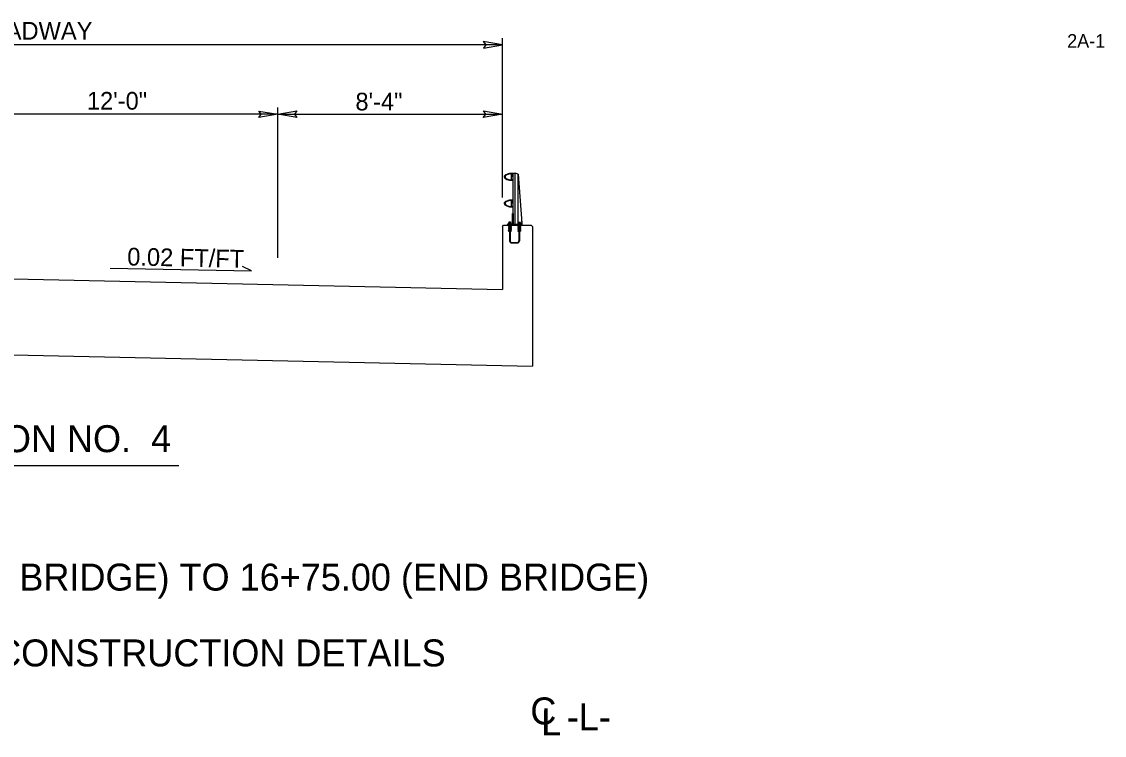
# Model space of a CAD drawing. Extents: x 1901984 to 1902132, y 194049 to 194156.
# Drawn here: x 1902088.64 to 1902128.82, y 194129.22 to 194155.68 of the extents above; entities that cross this region are included whole.
import ezdxf

# ---------------------------------------------------------------- set-up
doc = ezdxf.new("R2010")
doc.units = 0
for name, color, linetype in [('Old_Level_1', 7, 'Continuous'), ('Old_Level_11', 7, 'Continuous'), ('Old_Level_2', 7, 'Continuous'), ('Old_Level_44', 7, 'Continuous'), ('Scratch_Level_3', 7, 'Continuous'), ('Sheet PE Seal Cell', 7, 'Continuous')]:
    doc.layers.add(name, color=color, linetype=linetype)

# ---------------------------------------------------------------- blocks, each defined once
blk = doc.blocks.new('TERMINATOR')
at = {"layer": 'Scratch_Level_3'}
blk.add_lwpolyline([(-0.469, 0.081), (0, 0), (-0.471, -0.083), (-0.411, 0)], close=True, dxfattribs=at)

msp = doc.modelspace()

# ---------------------------------------------------------------- linework, layer by layer
at = {"layer": 'Old_Level_1'}
for p, q in [((1902106.478, 194154.823), (1902065.811, 194154.823)), ((1902106.478, 194149.16), (1902106.478, 194155.073)), ((1902098.144, 194146.923), (1902098.144, 194152.498)), ((1902098.144, 194152.248), (1902086.144, 194152.248)), ((1902098.144, 194152.249), (1902106.478, 194152.249)), ((1902091.931, 194146.546), (1902097.164, 194146.441)), ((1902097.164, 194146.441), (1902096.83, 194146.608)), ((1902086.144, 194146.196), (1902106.478, 194145.745)), ((1902086.563, 194143.369), (1902107.596, 194142.901))]:
    msp.add_line(p, q, dxfattribs=at)
at = {"layer": 'Old_Level_11'}
msp.add_line((1902077.852, 194139.224), (1902094.478, 194139.224), dxfattribs=at)
at = {"layer": 'Sheet PE Seal Cell'}
for p, q in [((1902106.813, 194150.028), (1902106.813, 194149.926)), ((1902106.876, 194150.059), (1902106.952, 194150.059)), ((1902106.876, 194148.176), (1902106.876, 194150.059)), ((1902107.066, 194150.022), (1902106.952, 194150.059)), ((1902106.952, 194148.176), (1902106.952, 194150.059)), ((1902107.066, 194148.176), (1902107.066, 194150.022)), ((1902107.066, 194150.022), (1902107.197, 194148.214)), ((1902106.813, 194149.824), (1902106.813, 194149.926)), ((1902106.813, 194149.041), (1902106.813, 194148.939)), ((1902106.813, 194148.837), (1902106.813, 194148.939)), ((1902107.066, 194149.158), (1902107.07, 194149.158)), ((1902106.478, 194148.089), (1902106.526, 194148.138)), ((1902106.478, 194148.089), (1902106.478, 194145.745)), ((1902106.526, 194148.138), (1902107.547, 194148.138)), ((1902106.705, 194148.102), (1902106.805, 194148.102)), ((1902106.705, 194148.091), (1902106.805, 194148.091)), ((1902106.705, 194148.058), (1902106.747, 194148.058)), ((1902106.705, 194148.047), (1902106.747, 194148.047)), ((1902106.705, 194148.013), (1902106.747, 194148.013)), ((1902106.705, 194148.002), (1902106.747, 194148.002)), ((1902106.727, 194148.08), (1902106.747, 194148.08)), ((1902106.727, 194148.069), (1902106.747, 194148.069)), ((1902106.727, 194148.035), (1902106.747, 194148.035)), ((1902106.727, 194148.024), (1902106.747, 194148.024)), ((1902106.727, 194147.991), (1902106.747, 194147.991)), ((1902106.727, 194147.98), (1902106.747, 194147.98)), ((1902106.73, 194148.102), (1902106.73, 194148.186)), ((1902106.732, 194148.226), (1902106.732, 194148.262)), ((1902106.732, 194148.262), (1902106.775, 194148.262)), ((1902106.747, 194148.08), (1902106.763, 194148.08)), ((1902106.747, 194148.08), (1902106.747, 194147.549)), ((1902106.763, 194148.08), (1902106.783, 194148.08)), ((1902106.763, 194148.08), (1902106.763, 194147.549)), ((1902106.763, 194148.069), (1902106.783, 194148.069)), ((1902106.763, 194148.058), (1902106.805, 194148.058)), ((1902106.763, 194148.047), (1902106.805, 194148.047)), ((1902106.763, 194148.035), (1902106.783, 194148.035)), ((1902106.763, 194148.024), (1902106.783, 194148.024)), ((1902106.763, 194148.013), (1902106.805, 194148.013)), ((1902106.763, 194148.002), (1902106.805, 194148.002)), ((1902106.763, 194147.991), (1902106.783, 194147.991)), ((1902106.763, 194147.98), (1902106.783, 194147.98)), ((1902106.775, 194148.262), (1902106.775, 194148.226)), ((1902106.777, 194148.102), (1902106.777, 194148.186)), ((1902107.053, 194148.102), (1902107.154, 194148.102)), ((1902107.053, 194148.091), (1902107.154, 194148.091)), ((1902107.053, 194148.058), (1902107.095, 194148.058)), ((1902107.053, 194148.047), (1902107.095, 194148.047)), ((1902107.053, 194148.013), (1902107.095, 194148.013)), ((1902107.053, 194148.002), (1902107.095, 194148.002)), ((1902107.076, 194148.08), (1902107.095, 194148.08)), ((1902107.076, 194148.069), (1902107.095, 194148.069)), ((1902107.076, 194148.035), (1902107.095, 194148.035)), ((1902107.076, 194148.024), (1902107.095, 194148.024)), ((1902107.076, 194147.991), (1902107.095, 194147.991)), ((1902107.076, 194147.98), (1902107.095, 194147.98)), ((1902107.081, 194148.217), (1902107.081, 194148.252)), ((1902107.081, 194148.252), (1902107.124, 194148.252)), ((1902107.081, 194148.093), (1902107.081, 194148.176)), ((1902107.095, 194148.08), (1902107.112, 194148.08)), ((1902107.095, 194148.08), (1902107.095, 194147.549)), ((1902107.112, 194148.08), (1902107.131, 194148.08)), ((1902107.112, 194148.08), (1902107.112, 194147.549)), ((1902107.112, 194148.069), (1902107.131, 194148.069)), ((1902107.112, 194148.058), (1902107.154, 194148.058)), ((1902107.112, 194148.047), (1902107.154, 194148.047)), ((1902107.112, 194148.035), (1902107.131, 194148.035)), ((1902107.112, 194148.024), (1902107.131, 194148.024)), ((1902107.112, 194148.013), (1902107.154, 194148.013)), ((1902107.112, 194148.002), (1902107.154, 194148.002)), ((1902107.112, 194147.991), (1902107.131, 194147.991)), ((1902107.112, 194147.98), (1902107.131, 194147.98)), ((1902107.124, 194148.252), (1902107.124, 194148.217)), ((1902107.125, 194148.093), (1902107.125, 194148.176)), ((1902107.194, 194148.235), (1902107.194, 194148.268)), ((1902107.197, 194148.176), (1902107.197, 194148.214)), ((1902107.547, 194148.138), (1902107.596, 194148.089)), ((1902107.596, 194148.089), (1902107.596, 194142.901)), ((1902106.705, 194147.969), (1902106.747, 194147.969)), ((1902106.705, 194147.958), (1902106.747, 194147.958)), ((1902106.705, 194147.924), (1902106.747, 194147.924)), ((1902106.705, 194147.913), (1902106.747, 194147.913)), ((1902106.727, 194147.946), (1902106.747, 194147.946)), ((1902106.727, 194147.935), (1902106.747, 194147.935)), ((1902106.763, 194147.969), (1902106.805, 194147.969)), ((1902106.763, 194147.958), (1902106.805, 194147.958)), ((1902106.763, 194147.946), (1902106.783, 194147.946)), ((1902106.763, 194147.935), (1902106.783, 194147.935)), ((1902106.763, 194147.924), (1902106.805, 194147.924)), ((1902106.763, 194147.913), (1902106.805, 194147.913)), ((1902107.053, 194147.969), (1902107.095, 194147.969)), ((1902107.053, 194147.958), (1902107.095, 194147.958)), ((1902107.053, 194147.924), (1902107.095, 194147.924)), ((1902107.053, 194147.913), (1902107.095, 194147.913)), ((1902107.076, 194147.946), (1902107.095, 194147.946)), ((1902107.076, 194147.935), (1902107.095, 194147.935)), ((1902107.112, 194147.969), (1902107.154, 194147.969)), ((1902107.112, 194147.958), (1902107.154, 194147.958)), ((1902107.112, 194147.946), (1902107.131, 194147.946)), ((1902107.112, 194147.935), (1902107.131, 194147.935)), ((1902107.112, 194147.924), (1902107.154, 194147.924)), ((1902107.112, 194147.913), (1902107.154, 194147.913)), ((1902106.817, 194147.496), (1902107.042, 194147.496)), ((1902106.817, 194147.479), (1902107.042, 194147.479))]:
    msp.add_line(p, q, dxfattribs=at)
for points in [[(1902106.876, 194149.796), (1902106.876, 194149.844), (1902106.856, 194149.844), (1902106.856, 194149.836), (1902106.858, 194149.836), (1902106.858, 194149.816), (1902106.826, 194149.816), (1902106.822, 194149.847), (1902106.822, 194149.926), (1902106.822, 194150.005), (1902106.826, 194150.036), (1902106.858, 194150.036), (1902106.858, 194150.016), (1902106.856, 194150.016), (1902106.856, 194150.008), (1902106.876, 194150.008), (1902106.876, 194150.057)], [(1902106.876, 194148.808), (1902106.876, 194148.857), (1902106.856, 194148.857), (1902106.856, 194148.849), (1902106.858, 194148.849), (1902106.858, 194148.829), (1902106.826, 194148.829), (1902106.822, 194148.86), (1902106.822, 194148.939), (1902106.822, 194149.018), (1902106.826, 194149.049), (1902106.858, 194149.049), (1902106.858, 194149.029), (1902106.856, 194149.029), (1902106.856, 194149.02), (1902106.876, 194149.02), (1902106.876, 194149.069)], [(1902106.683, 194148.138), (1902106.683, 194148.186), (1902106.857, 194148.186), (1902106.857, 194148.572), (1902106.876, 194148.572), (1902106.876, 194148.176), (1902107.188, 194148.176), (1902107.188, 194148.204), (1902107.197, 194148.204), (1902107.197, 194148.138), (1902107.047, 194148.138), (1902107.047, 194148.164), (1902106.895, 194148.164), (1902106.895, 194148.138), (1902106.683, 194148.138)], [(1902106.705, 194148.102), (1902106.705, 194148.091), (1902106.727, 194148.08), (1902106.727, 194148.069), (1902106.705, 194148.058), (1902106.705, 194148.047), (1902106.727, 194148.035), (1902106.727, 194148.024), (1902106.705, 194148.013), (1902106.705, 194148.002), (1902106.727, 194147.991), (1902106.727, 194147.98), (1902106.705, 194147.969), (1902106.705, 194147.958), (1902106.727, 194147.946), (1902106.727, 194147.935), (1902106.705, 194147.924), (1902106.705, 194147.913)], [(1902106.71, 194148.185), (1902106.71, 194148.194), (1902106.753, 194148.194), (1902106.796, 194148.194), (1902106.796, 194148.185)], [(1902106.722, 194148.193), (1902106.722, 194148.221), (1902106.727, 194148.226), (1902106.78, 194148.226), (1902106.785, 194148.221), (1902106.785, 194148.193), (1902106.722, 194148.193), (1902106.743, 194148.193), (1902106.743, 194148.221), (1902106.737, 194148.226), (1902106.743, 194148.221), (1902106.748, 194148.226), (1902106.759, 194148.226), (1902106.764, 194148.221), (1902106.764, 194148.193), (1902106.764, 194148.221), (1902106.769, 194148.226)], [(1902106.805, 194148.102), (1902106.805, 194148.091), (1902106.783, 194148.08), (1902106.783, 194148.069), (1902106.805, 194148.058), (1902106.805, 194148.047), (1902106.783, 194148.035), (1902106.783, 194148.024), (1902106.805, 194148.013), (1902106.805, 194148.002), (1902106.783, 194147.991), (1902106.783, 194147.98), (1902106.805, 194147.969), (1902106.805, 194147.958), (1902106.783, 194147.946), (1902106.783, 194147.935), (1902106.805, 194147.924), (1902106.805, 194147.913)], [(1902107.053, 194148.102), (1902107.053, 194148.091), (1902107.075, 194148.08), (1902107.075, 194148.069), (1902107.053, 194148.058), (1902107.053, 194148.047), (1902107.075, 194148.035), (1902107.075, 194148.024), (1902107.053, 194148.013), (1902107.053, 194148.002), (1902107.075, 194147.991), (1902107.075, 194147.98), (1902107.053, 194147.969), (1902107.053, 194147.958), (1902107.075, 194147.946), (1902107.075, 194147.935), (1902107.053, 194147.924), (1902107.053, 194147.913)], [(1902107.06, 194148.175), (1902107.06, 194148.184), (1902107.103, 194148.184), (1902107.145, 194148.184), (1902107.145, 194148.175)], [(1902107.071, 194148.184), (1902107.071, 194148.211), (1902107.076, 194148.217), (1902107.129, 194148.217), (1902107.134, 194148.211), (1902107.134, 194148.184), (1902107.071, 194148.184), (1902107.092, 194148.184), (1902107.092, 194148.211), (1902107.086, 194148.217), (1902107.092, 194148.211), (1902107.097, 194148.217), (1902107.108, 194148.217), (1902107.113, 194148.211), (1902107.113, 194148.184), (1902107.113, 194148.211), (1902107.119, 194148.217)], [(1902107.154, 194148.102), (1902107.154, 194148.091), (1902107.131, 194148.08), (1902107.131, 194148.069), (1902107.154, 194148.058), (1902107.154, 194148.047), (1902107.131, 194148.035), (1902107.131, 194148.024), (1902107.154, 194148.013), (1902107.154, 194148.002), (1902107.131, 194147.991), (1902107.131, 194147.98), (1902107.154, 194147.969), (1902107.154, 194147.958), (1902107.131, 194147.946), (1902107.131, 194147.935), (1902107.154, 194147.924), (1902107.154, 194147.913)]]:
    msp.add_lwpolyline(points, dxfattribs=at)
for centre in [(1902106.714, 194147.941), (1902107.145, 194147.941)]:
    msp.add_circle(centre, 0.00834, dxfattribs=at)
for centre, radius, start, end in [((1902106.805, 194150.028), 0.00783, 0, 90), ((1902106.805, 194149.824), 0.00783, 270, 360), ((1902106.805, 194149.041), 0.00783, 0, 90), ((1902106.805, 194148.837), 0.00783, 270, 360), ((1902106.817, 194147.549), 0.07, 180, 270), ((1902106.817, 194147.549), 0.0534, 180, 270), ((1902107.042, 194147.549), 0.0534, 270, 0), ((1902107.042, 194147.549), 0.07, 270, 0)]:
    msp.add_arc(centre, radius, start, end, dxfattribs=at)
for centre, major_axis, ratio, start_param, end_param in [((1902106.877, 194149.926), (-0.334, 0), 0.39036, 4.712404, 6.283584), ((1902106.805, 194149.926), (-0.222, 0), 0.495501, 4.712489, 6.283652), ((1902106.877, 194149.926), (-0.334, 0), 0.39036, 0.000398, 1.570782), ((1902106.805, 194149.926), (-0.222, 0), 0.495501, 0.000467, 1.570696), ((1902106.877, 194148.939), (-0.334, 0), 0.39036, 4.712404, 6.283584), ((1902106.877, 194148.939), (-0.334, 0), 0.39036, 0.000398, 1.570782), ((1902106.805, 194148.939), (-0.222, 0), 0.495501, 4.712489, 6.283652), ((1902106.805, 194148.939), (-0.222, 0), 0.495501, 0.000467, 1.570696)]:
    msp.add_ellipse(centre, major_axis=major_axis, ratio=ratio, start_param=start_param, end_param=end_param, dxfattribs=at)

# ---------------------------------------------------------------- block references
at = {"layer": 'Old_Level_1', "xscale": 1.5}
for p, yscale in [((1902106.478, 194154.823), -1.5), ((1902098.144, 194152.248), 1.5), ((1902106.478, 194152.249), 1.5)]:
    msp.add_blockref('TERMINATOR', p, dxfattribs=dict(at, yscale=yscale))
at = {"layer": 'Old_Level_1', "xscale": 1.5, "yscale": 1.5, "rotation": 180}
msp.add_blockref('TERMINATOR', (1902098.144, 194152.249), dxfattribs=at)

# ---------------------------------------------------------------- texts
at = {"layer": 'Old_Level_1'}
for s, p in [('40\'-8"   CLEAR ROADWAY', (1902080.601, 194155.017)), ('12\'-0" ', (1902091.062, 194152.42)), ('8\'-4"', (1902101.026, 194152.39))]:
    msp.add_text(s, height=0.656, dxfattribs=at).set_placement(p)
at = {"layer": 'Old_Level_11'}
for s, p in [('TYPICAL SECTION NO.  4', (1902078.063, 194139.718)), ('-L- STA 14+85.00 (BEGIN BRIDGE) TO 16+75.00 (END BRIDGE)', (1902072.614, 194134.585)), ('SEE STRUCTURE PLANS FOR CONSTRUCTION DETAILS', (1902068.041, 194131.773))]:
    msp.add_text(s, height=1, dxfattribs=at).set_placement(p)
at = {"layer": 'Old_Level_2'}
for s, height, rotation, p in [('0.02 FT/FT', 0.656, 358.8656, (1902092.554, 194146.644)), ('-L-', 1, 359.9469, (1902108.868, 194129.4)), ('L', 1, 359.9469, (1902107.919, 194129.218))]:
    msp.add_text(s, height=height, rotation=rotation, dxfattribs=at).set_placement(p)
msp.add_text('C', height=1, dxfattribs=at).set_placement((1902107.517, 194129.622))
at = {"layer": 'Old_Level_44'}
msp.add_text('2A-1', height=0.5, dxfattribs=at).set_placement((1902127.436, 194154.719))

doc.saveas('drawing.dxf')
